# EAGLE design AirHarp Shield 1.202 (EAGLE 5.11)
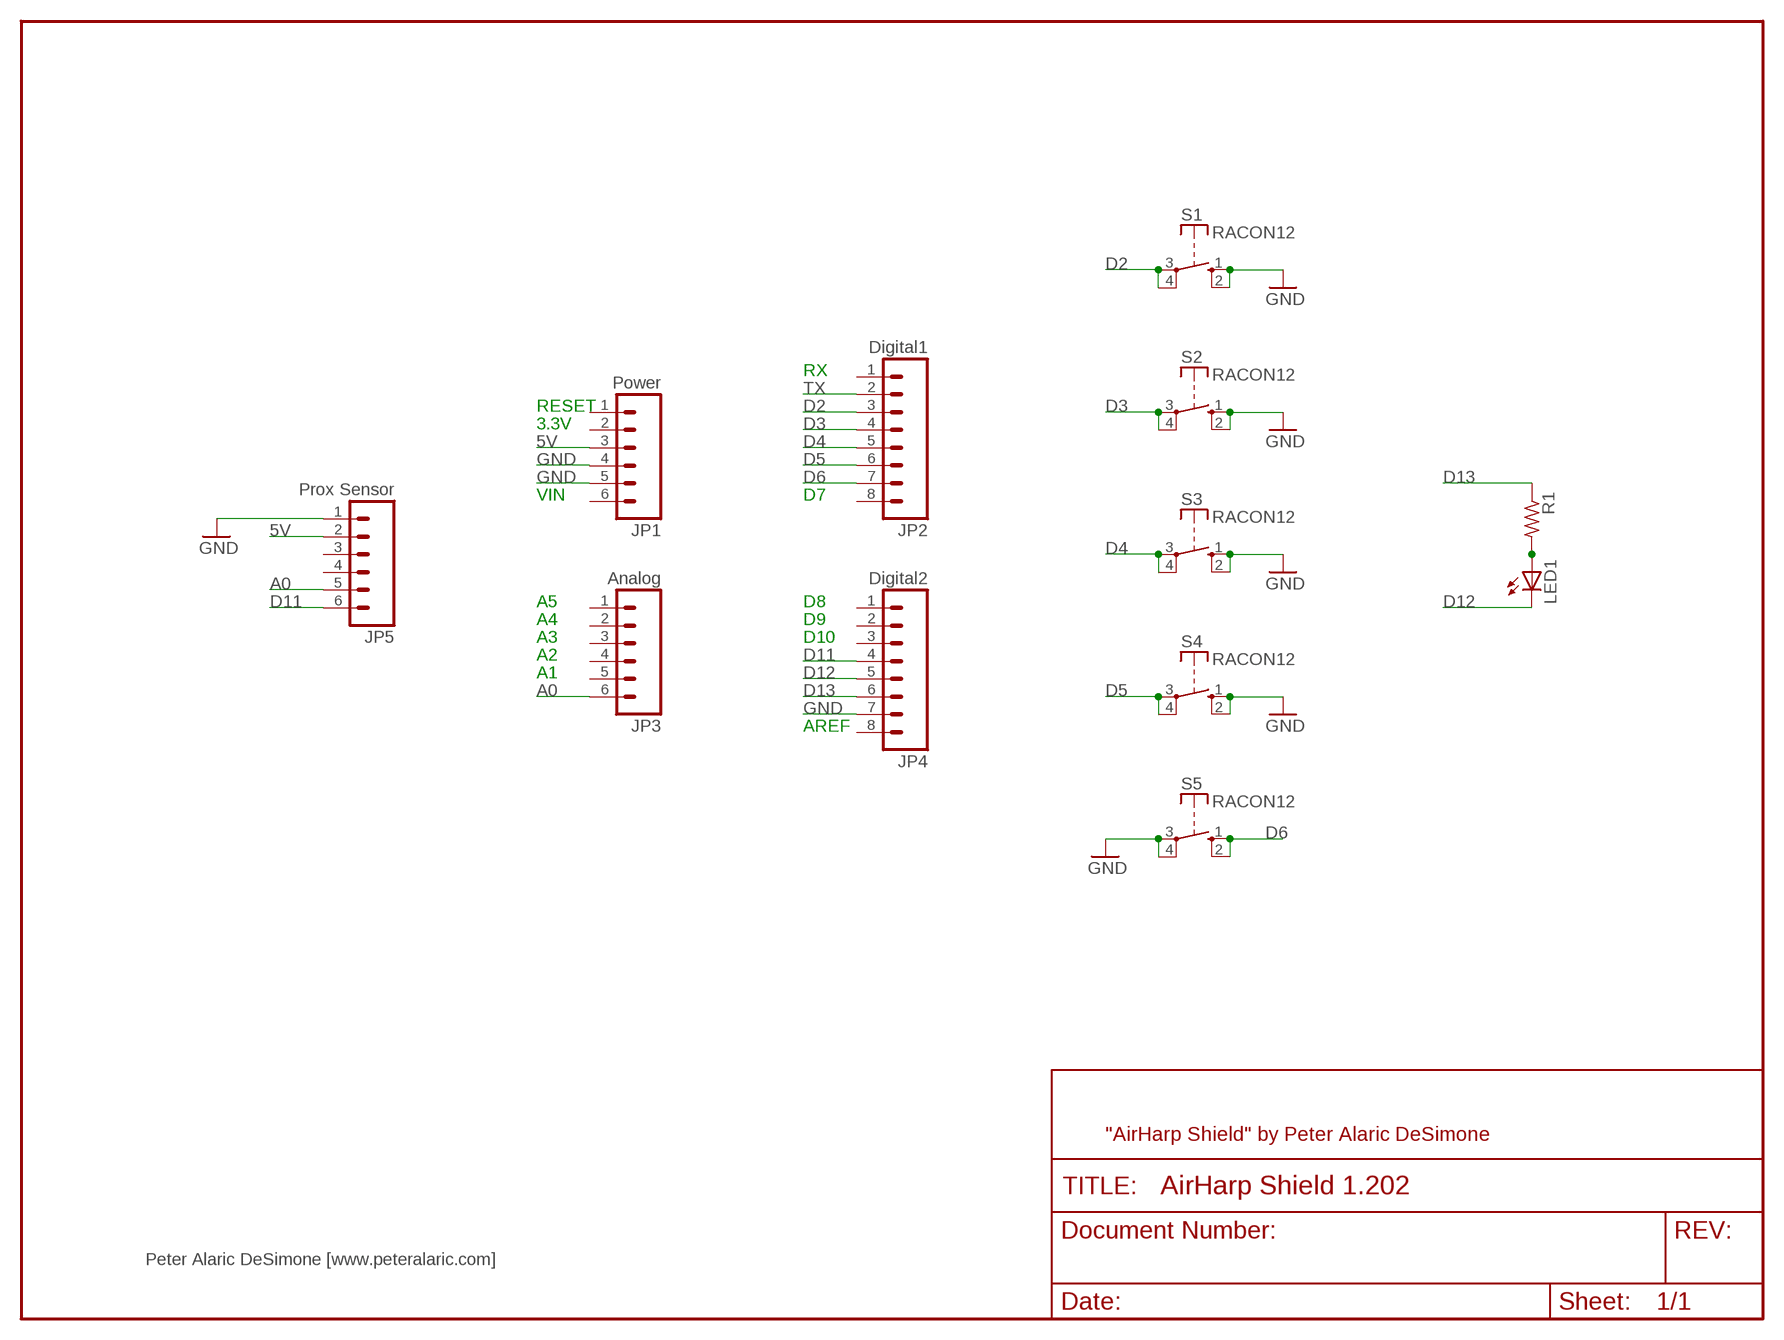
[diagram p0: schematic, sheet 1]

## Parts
JP1  Power  M06SIP  [1X06]
JP2  Digital1  M08  [1X08]
JP3  Analog  M06SIP  [1X06]
JP4  Digital2  M08  [1X08]
JP5  Prox Sensor  M06SIP  [1X06]
LED1  LED10MM  [LED10MM]
R1  R-US_0207/7  [0207/7]
S1  RACON12  [RACON12]
S2  RACON12  [RACON12]
S3  RACON12  [RACON12]
S4  RACON12  [RACON12]
S5  RACON12  [RACON12]

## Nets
5V: JP1.3 JP5.2
A0: JP3.6 JP5.5
D2: JP2.3 S1.3(P) S1.4(P)
D3: JP2.4 S2.3(P) S2.4(P)
D4: JP2.5 S3.3(P) S3.4(P)
D5: JP2.6 S4.3(P) S4.4(P)
D6: JP2.7 S5.1(S) S5.2(S)
D11: JP4.4 JP5.6
D12: JP4.5 LED1.K(C)
D13: JP4.6 R1.1
GND: JP1.4 JP1.5 JP4.7 JP5.1 S1.1(S) S1.2(S) S2.1(S) S2.2(S) S3.1(S) S3.2(S) S4.1(S) S4.2(S) S5.3(P) S5.4(P)
N$1: LED1.A R1.2
TX: JP2.2
Unconnected: JP1.1 JP1.2 JP1.6 JP2.1 JP2.8 JP3.1 JP3.2 JP3.3 JP3.4 JP3.5 JP4.1 JP4.2 JP4.3 JP4.8 JP5.3 JP5.4

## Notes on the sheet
- RX
- RESET
- 3.3V
- VIN | D7
- A5 | D8
- A4 | D9
- A3 | D10
- A2
- A1
- AREF
- "AirHarp Shield" by Peter Alaric DeSimone
- Peter Alaric DeSimone [www.peteralaric.com]

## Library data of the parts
JP1 JP3 JP5 = SparkFun:M06: Header 6 Standard 6-pin 0.1" header. Use with straight break away headers (SKU : PRT-00116), right angle break away headers (PRT-00553), swiss pins (PRT-00743), machine pins (PRT-00117), and female headers (PRT-00115). Molex polarized connector foot print use with SKU : PRT-08094 with associated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
JP2 JP4 = SparkFun:M08: Header 8 Standard 8-pin 0.1" header. Use with straight break away headers (SKU : PRT-00116), right angle break away headers (PRT-00553), swiss pins (PRT-00743), machine pins (PRT-00117), and female headers (PRT-00115).
LED1 = led:LED: LED
R1 = resistor:R-US_: RESISTOR, American symbol
S1-S5 = switch-misc:RACON12: ITT SWITCH

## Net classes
1 power: width 0.254 mm

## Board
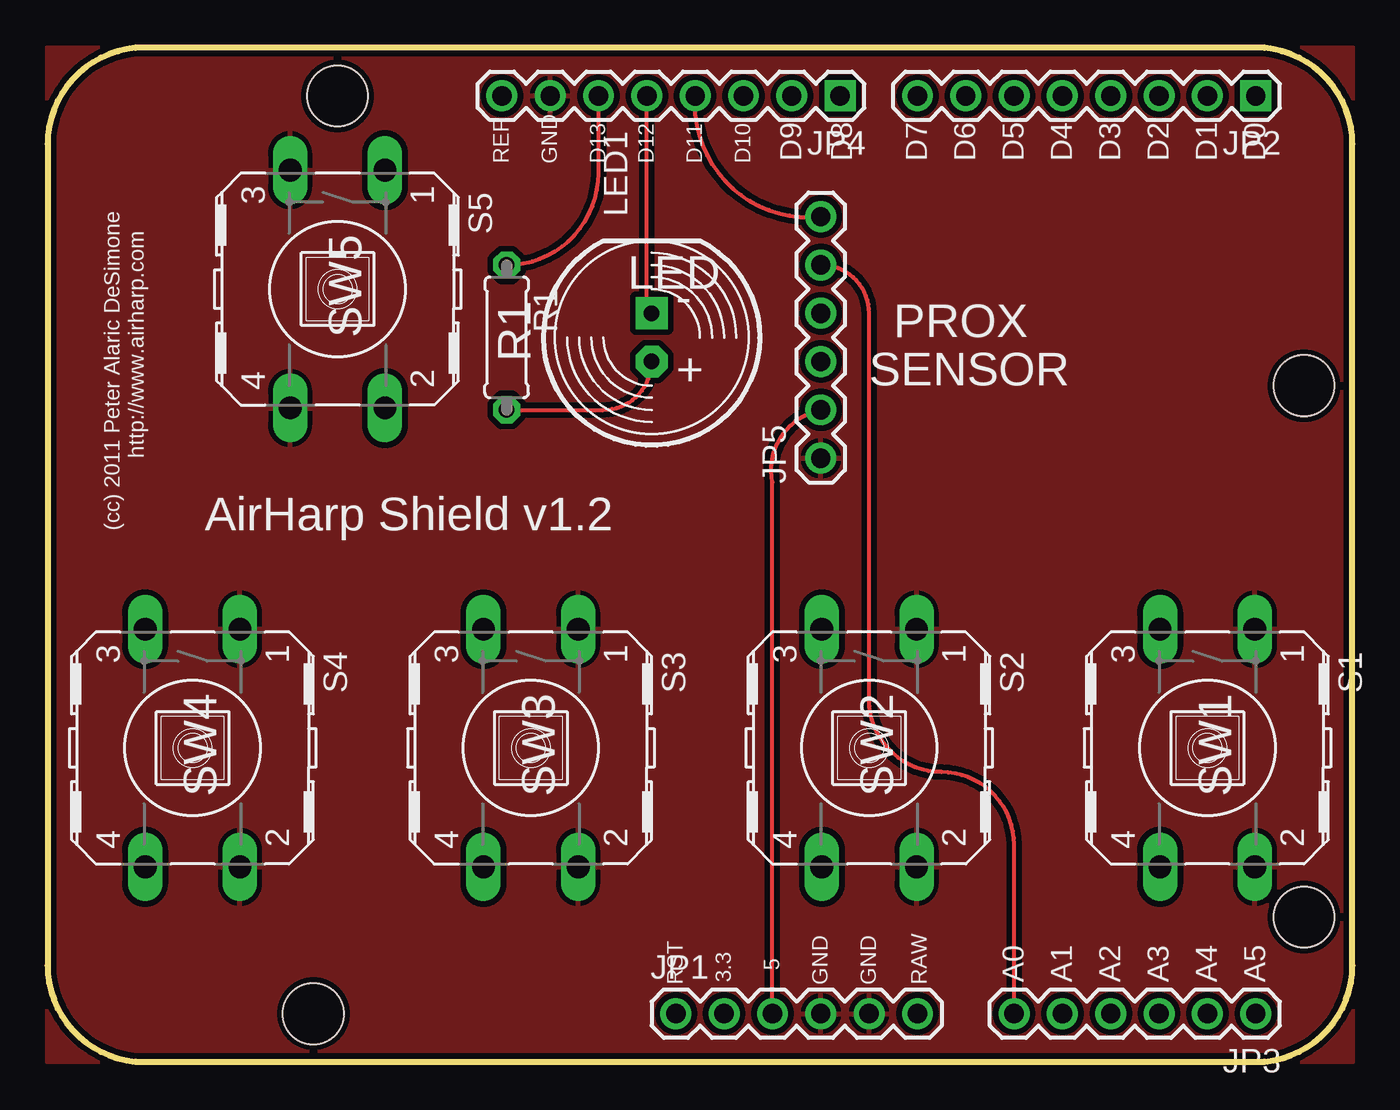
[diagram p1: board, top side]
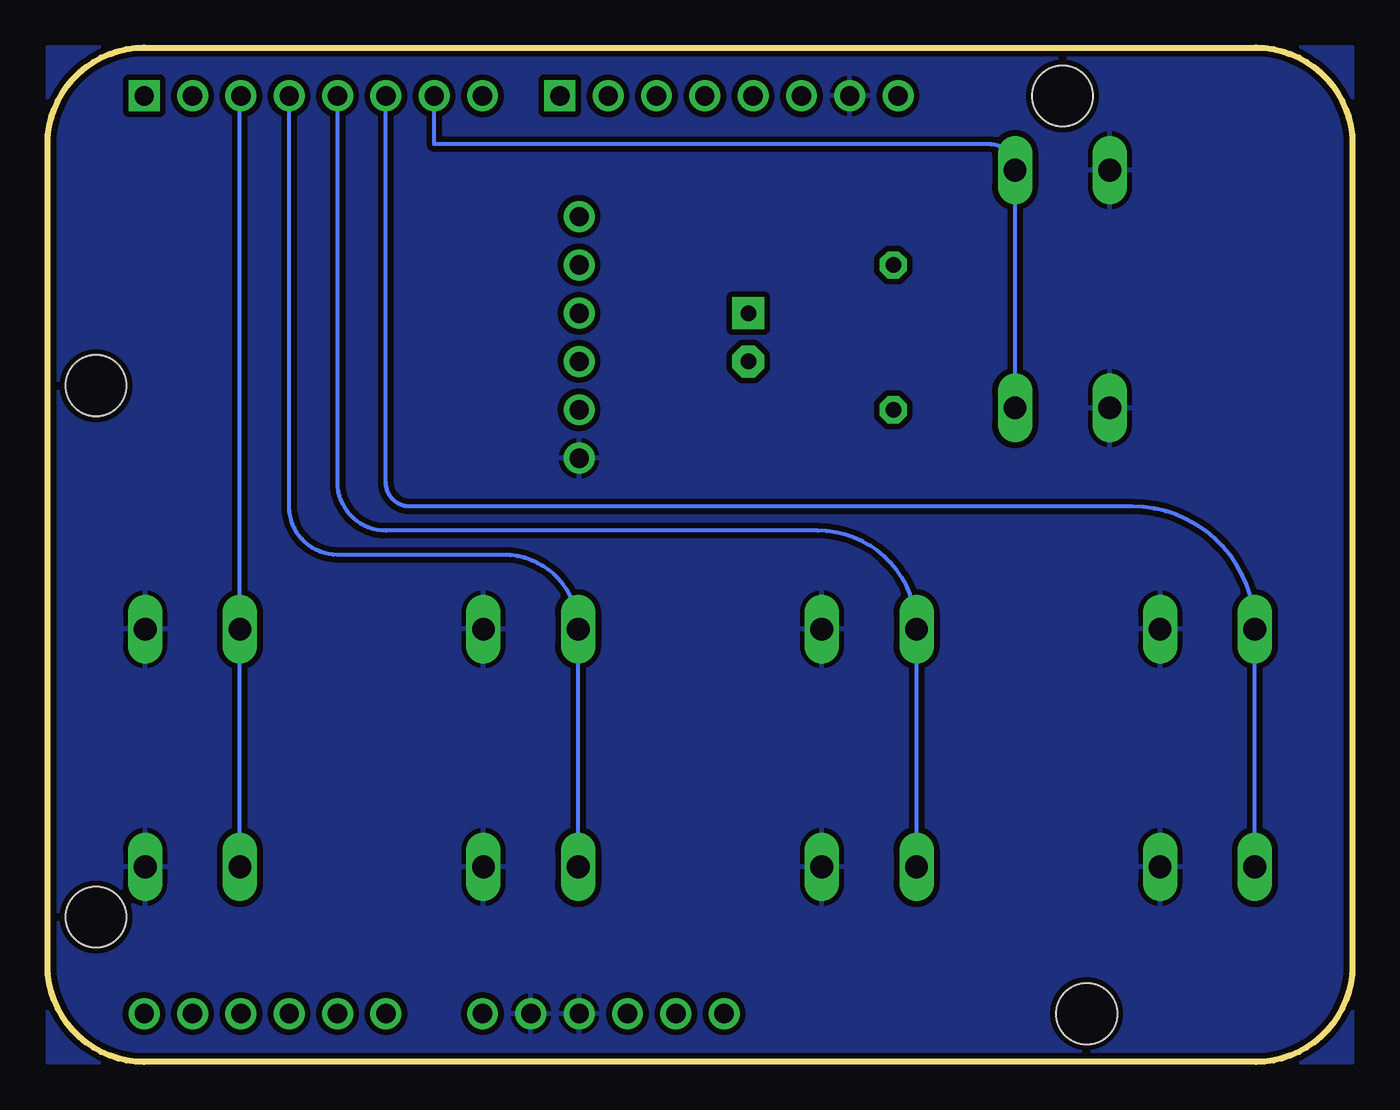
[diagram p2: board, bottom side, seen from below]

Size 68.58 x 53.34 mm. Coordinates in mm from the lower left corner, seen from the top.
Outline: 63.5,0 arc90 68.58,5.08 68.58,48.26 arc90 63.5,53.34 5.08,53.34 arc90 0,48.26 0,5.08 arc90 5.08,0 63.5,0
Copper layers (1*16): Top 0.035mm / dielectric 1.5mm / Bottom 0.035mm
Design rules "SparkFun": minimum track width 8mil, minimum drill 20mil, track to track 8mil, track to pad 8mil, pad to pad 8mil, via to via 8mil, smd to smd 8mil, copper to edge 10mil, drill to drill 8mil, minimum pad ring 12mil, minimum via ring 10mil, stop-mask expansion 4mil, vias tented up to drill 20mil, thermal gap 10mil
Holes 3.2 mm at 66.04,7.62 15.24,50.8 66.04,35.56 13.97,2.54

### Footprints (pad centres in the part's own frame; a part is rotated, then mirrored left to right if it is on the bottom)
1X06 = drill 1.016 round: 1 0,0; 2 2.54,0; 3 5.08,0; 4 7.62,0; 5 10.16,0; 6 12.7,0
1X08 = drill 1.016 square: 1 0,0 | drill 1.016 round: 2 2.54,0; 3 5.08,0; 4 7.62,0; 5 10.16,0; 6 12.7,0; 7 15.24,0; 8 17.78,0
LED10MM = drill 0.813 pad 1.676 octagon: A -1.27,0 | drill 0.813 pad 1.676 square: K 1.27,0
0207/7 = drill 0.813 octagon: 1 -3.81,0; 2 3.81,0
RACON12 = drill 1.194 long: 1 -6.248,2.489; 2 6.248,2.489; 3 -6.248,-2.489; 4 6.248,-2.489

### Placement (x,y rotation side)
JP1  33.02,2.54 0 top
JP2  63.5,50.8 180 top
JP3  63.5,2.54 180 top
JP4  41.66,50.8 180 top
JP5  40.64,31.75 90 top
LED1  31.75,38.1 90 top
R1  24.13,38.1 270 top
S1  60.96,16.51 270 top
S2  43.18,16.51 270 top
S3  25.4,16.51 270 top
S4  7.62,16.51 270 top
S5  15.24,40.64 270 top

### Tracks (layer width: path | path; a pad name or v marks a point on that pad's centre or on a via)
5V
  Top 0.203: JP5.2 arc90 38.1,30.48 JP1.3
A0
  Top 0.203: JP5.5 arc-90 43.18,39.37 43.18,19.05 arc90 46.99,15.24 arc-90 50.8,11.43 JP3.6
D2
  Bottom 0.203: JP2.3 58.47,50.8 S1.3 S1.4
D3
  Bottom 0.203: S2.4 S2.3 arc-90 44.6,26.67 53.34,26.67 arc90 55.88,29.21 JP2.4
D4
  Bottom 0.203: JP2.5 53.34,30.48 arc-90 50.8,27.94 28.09,27.94 arc90 S3.3 S3.4
D5
  Bottom 0.203: JP2.6 50.8,30.48 arc-90 49.53,29.21 11.58,29.21 arc90 S4.3 S4.4
D6
  Bottom 0.203: JP2.7 48.26,48.26 19.1,48.26 arc90 S5.1 S5.2
D11
  Top 0.203: JP5.6 arc-90 34.04,49.78 JP4.4
D12
  Top 0.203: JP4.5 31.5,39.62 arc90 LED1.K
D13
  Top 0.203: JP4.6 28.96,46.74 arc-90 R1.1
GND
  Top 0.406: 26.42,50.11 JP4.7
  pour Top (isolate 0.305): 0,53.34 68.58,53.34 68.58,0 0,0
  pour Bottom (isolate 0.305): 0,53.34 68.58,53.34 68.58,0 0,0
N$1
  Top 0.203: LED1.A arc-90 29.21,34.29 R1.2

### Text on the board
tPlace: REF | GND | D13 | D12 | D11 | D10 | D9 | D8 | D7 | D6 | D5 | D4 | D3 | D2 | D1 | D0 | 5 | RST | 3.3 | GND | GND | RAW | A0 | A1 | A2 | A3 | A4 | A5
_tsilk: LED | - | SW5 | PROX | R1 | + | SENSOR | http://www.airharp.com | (cc) 2011 Peter Alaric DeSimone | AirHarp Shield v1.2 | SW4 | SW3 | SW2 | SW1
